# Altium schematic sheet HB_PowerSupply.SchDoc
size A4
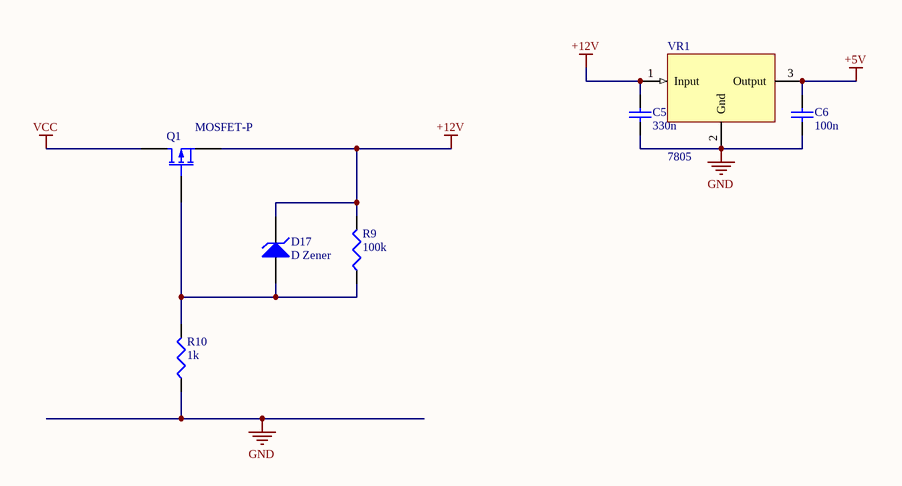
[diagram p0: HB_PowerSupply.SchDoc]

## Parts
C5  value 330n  [C1206]  (hidden comment: Cap_330n)
C6  value 100n  [C1206]  (hidden comment: Cap_100n)
D17  D Zener  [SOD-123]
Q1  MOSFET-P  [TO-220-AB]
R9  value 100k  [6-0805_L]  (hidden comment: Res_100k)
R10  value 1k  [6-0805_L]  (hidden comment: Res_1k)
VR1  7805  [TO-220AB]

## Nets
+5V: C6.1 VR1.3(Output)
+12V: C5.1 D17.1(K) Q1.S R9.2 VR1.1(Input)
GND: C5.2 C6.2 R10.1 VR1.2(Gnd)
VCC: Q1.D
NetD17_2: D17.2(A) Q1.G R9.1 R10.2

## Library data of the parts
C5 = Cap_330n: Condensateur
C6 = Cap_100n: Condensateur
D17 = D Zener: Zener Diode
Q1 = MOSFET-P: P-Channel MOSFET
R9 = Res_100k: Résistance standard
R10 = Res_1k: Résistance standard
VR1 = 7805: Régulateur 5V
